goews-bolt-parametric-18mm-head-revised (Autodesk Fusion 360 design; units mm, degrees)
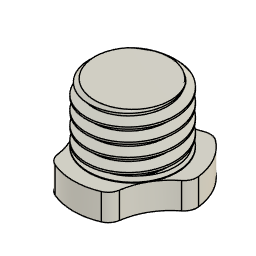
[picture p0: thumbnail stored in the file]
parameter "Boltlength" = 9
cylinder_primitive "CylinderPrimitive1" Height 9 (= "Boltlength") Diameter 14
thread "Thread1" ThreadOffset 0.1 ThreadLength 8.9 (= "Boltlength - 0.1 mm")
chamfer "Chamfer1" distance 1
sketch "Head" plane through (0, 0, 0) normal (0, 0, -1) x axis (1, 0, 0)
  line L1 (0, 9) -> (0, -9)
  line L2 (1, -7) -> (-1, 7)
  line L3 (-1, -7) -> (1, 7)
  line L4 (-9, 0) -> (9, 0)
  line L5 (0, -6.761) -> (0, 6.761)
  line L6 (0, 14) -> (0, -14)
  line L7 (-14.605, 18) -> (13.3677, 18)
  line L8 (0, 9) -> (0, -9)
  line L9 (6, -9) -> (0, -9)
  line L10 (0, -9) -> (6, -9)
  line L11 (-6, -9) -> (0, -9)
  circle C1 centre (0, 0) radius 6.761
  circle C2 centre (0, 0) radius 9
  arc A1 centre (0, -15.9198) radius 9.1588 clockwise from (-6, -9) to (6, -9)
  arc A2 centre (13.787, 7.9599) radius 9.1588 clockwise from (10.7942, -0.6962) to (4.7942, 9.6962)
  arc A3 centre (-13.787, 7.9599) radius 9.1588 clockwise from (-4.7942, 9.6962) to (-10.7942, -0.6962)
  point P5 (0, 9)
  point P4 (0, -9)
  point P10 (0, 0)
  point P2 (0, 0)
  point P12 (-9, 0)
  point P11 (9, 0)
  point P14 (0, -6.761)
  point P15 (0, 0)
  point P18 (0, 0)
  point P22 (0, 9)
  point P23 (0, 0)
  point P8 (1, -7)
  point P9 (-1, -7)
  point P7 (1, 7)
  point P13 (0, 6.761)
  point P16 (0, -14)
  point P17 (0, 14)
  point P21 (0, -9)
  point P24 (6, -9)
  point P25 (-6, -9)
  coincident C2 P5
  vertical L1
  coincident C2 P4
  coincident L2 P10
  coincident L3 P10
  coincident P2 P10
  coincident C2 P12
  coincident C2 P11
  coincident L1 P14
  coincident C1 P14
  coincident P10 P15
  midpoint L5 P15
  parallel L1 L6
  coincident P15 P18
  midpoint L6 P18
  coincident P5 P22
  parallel L1 L8
  coincident P18 P23
  midpoint L8 P23
  perpendicular L1 L9
  perpendicular L8 L11
  coincident P14 A1
  dimension "d7" = 2.239
  dimension "d9" distance P8 P9 = 2
  dimension "d10" distance P7 P8 = 14
  dimension "d25" distance P13 P14 = 13.522
  dimension "d27" distance P16 P17 = 28
  dimension "d28" distance P10 L7 = 18
  dimension "d33" distance P21 P24 = 6
  dimension "d34" distance P4 P25 = 6
  dimension "d44" diameter C2 = 18
  dimension "d36" value = 360 (= "C-Pattern1-Angle")
extrude "Extrude1" add sketch "Head" profile of C1 C2 A1 A2 A3 along normal blind 4
fillet "Fillet1" radius 2
sketch "Sketch4" plane through (0, 0, -4) normal (0, 0, -1) x axis (1, 0, 0)
  line L1 (4.8494, 0.0536) -> (2.4711, -4.173)
  line L2 (2.3783, 4.2265) -> (4.8494, 0.0536)
  line L3 (-2.4711, 4.173) -> (2.3783, 4.2265)
  line L4 (-4.8494, -0.0536) -> (-2.4711, 4.173)
  line L5 (-2.3783, -4.2265) -> (-4.8494, -0.0536)
  line L6 (2.4711, -4.173) -> (-2.3783, -4.2265)
  arc A1 centre (-6.9473, -0.857) radius 2 clockwise from (-8.9323, -1.1019) to (-8.1732, 0.7232)
  arc A2 centre (0, 0) radius 9 clockwise from (-5.4204, -7.1846) to (-8.9323, -1.1019)
  arc A3 centre (-4.2159, -5.588) radius 2 clockwise from (-3.4603, -7.4398) to (-5.4204, -7.1846)
  arc A4 centre (0, -15.9198) radius 9.1588 clockwise from (-3.4603, -7.4398) to (3.4603, -7.4398)
  arc A5 centre (4.2159, -5.588) radius 2 clockwise from (5.4204, -7.1846) to (3.4603, -7.4398)
  arc A6 centre (0, 0) radius 9 clockwise from (8.9323, -1.1019) to (5.4204, -7.1846)
  arc A7 centre (6.9473, -0.857) radius 2 clockwise from (8.1732, 0.7232) to (8.9323, -1.1019)
  arc A8 centre (13.787, 7.9599) radius 9.1588 clockwise from (8.1732, 0.7232) to (4.7129, 6.7166)
  arc A9 centre (2.7314, 6.4451) radius 2 clockwise from (3.5119, 8.2865) to (4.7129, 6.7166)
  arc A10 centre (0, 0) radius 9 clockwise from (-3.5119, 8.2865) to (3.5119, 8.2865)
  arc A11 centre (-2.7314, 6.4451) radius 2 clockwise from (-4.7129, 6.7166) to (-3.5119, 8.2865)
  arc A12 centre (-13.787, 7.9599) radius 9.1588 clockwise from (-4.7129, 6.7166) to (-8.1732, 0.7232)
  point P6 (0, 0)
  point P30 (0, 0)
  coincident P6 P30
  dimension "d39" distance P30 L6 = 4.2
extrude "Extrude6" cut sketch "Sketch4" profile of L1 L2 L3 L4 L5 L6 against normal blind 3.5
chamfer "Chamfer6" distance 0.5
component_from_bodies "Body->Comp"
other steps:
base_feature "Base Feature" bodies "Bolt"
create_component "CreateComponent1"
remove_body "RemoveBody1"
named bodies: "Bolt"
